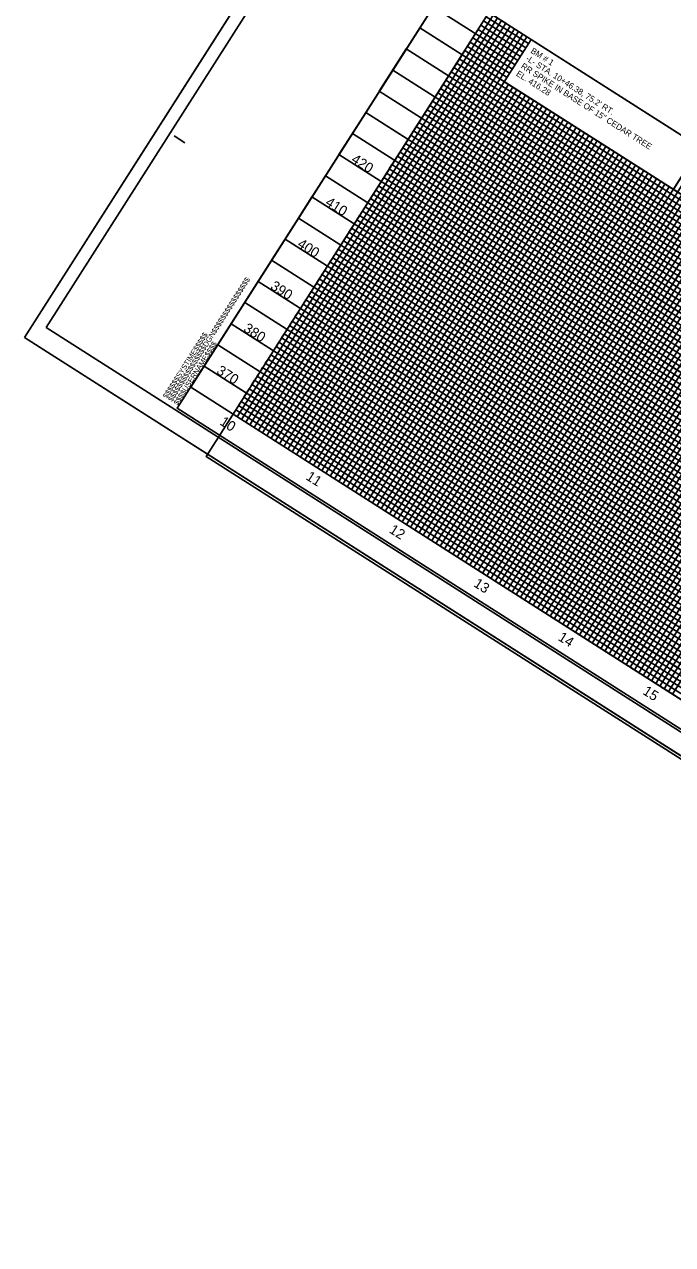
# Model space of a CAD drawing. Extents: x 2023536 to 2025544, y 819438 to 821266.
# Drawn here: x 2023536 to 2024183, y 819438 to 820655 of the extents above; entities that cross this region are included whole.
import ezdxf

# ---------------------------------------------------------------- set-up
doc = ezdxf.new("R2010")
doc.units = 0
for name, color, linetype in [('Default', 7, 'Continuous'), ('Exist Vertical Profile Horizontal Axis Label Major', 7, 'Continuous'), ('Exist Vertical Profile Vertical Axis Label', 7, 'Continuous'), ('Sheet Block System Information CELL', 7, 'Continuous'), ('Sheet Clip Boundary CELL', 7, 'Continuous'), ('Sheet Cutting Line CELL', 7, 'Continuous'), ('Sheet DOT Grid CELL', 7, 'Continuous'), ('Sheet Layout Profile Border Port 2', 7, 'Continuous'), ('Sheet Plan And Profile CELL', 7, 'Continuous'), ('Sheet Plot Border Inside CELL', 7, 'Continuous'), ('Sheet Plot Border Outside CELL', 7, 'Continuous'), ('Sheet Profile Grid Major CELL', 7, 'Continuous'), ('Sheet Profile Grid Middle CELL', 7, 'Continuous'), ('Sheet Profile Grid Minor CELL', 7, 'Continuous')]:
    doc.layers.add(name, color=color, linetype=linetype)

msp = doc.modelspace()

# ---------------------------------------------------------------- linework, layer by layer
at = {"layer": 'Default'}
msp.add_lwpolyline([(2024041.6, 820640.3), (2024210.3, 820532.8), (2024183.4, 820490.6), (2024014.8, 820598.1)], close=True, dxfattribs=at)
at = {"layer": 'Sheet Block System Information CELL'}
msp.add_line((2023688.6, 820272.4), (2023688.6, 820272.4), dxfattribs=at)
at = {"layer": 'Sheet Clip Boundary CELL'}
for points in [[(2023957.3, 820694), (2024252.9, 821157.8), (2024518.4, 820988.6), (2024450.6, 820880.9), (2024650, 820753), (2024719.3, 820860.6), (2025349.2, 820459.2), (2025268.5, 820332.6), (2025437.2, 820225.1), (2025222.2, 819887.8)], [(2023972.6, 820625), (2025153.2, 819872.5), (2024897.9, 819472), (2023717.3, 820224.4)]]:
    msp.add_lwpolyline(points, close=True, dxfattribs=at)
at = {"layer": 'Sheet Cutting Line CELL'}
for p, q in [((2024124.6, 821266.3), (2023536.1, 820342.9)), ((2023536.1, 820342.9), (2024955.8, 819438.1))]:
    msp.add_line(p, q, dxfattribs=at)
at = {"layer": 'Sheet DOT Grid CELL'}
for p, q in [((2023957.3, 820694), (2024041.6, 820640.3)), ((2023999.5, 820667.1), (2023744.2, 820266.6)), ((2023930.4, 820651.9), (2025195.4, 819845.7)), ((2024041.6, 820640.3), (2023786.3, 820239.7)), ((2023903.6, 820609.7), (2025168.5, 819803.5)), ((2024056.9, 820571.2), (2023828.5, 820212.8)), ((2023876.7, 820567.5), (2025141.6, 819761.3)), ((2024099.1, 820544.4), (2023870.7, 820186)), ((2024210.3, 820532.8), (2023955, 820132.2)), ((2023849.8, 820525.4), (2025114.8, 819719.2)), ((2024141.3, 820517.5), (2023912.8, 820159.1)), ((2024252.5, 820505.9), (2023997.2, 820105.3)), ((2023822.9, 820483.2), (2025087.9, 819677)), ((2024294.6, 820479), (2024039.3, 820078.5)), ((2024336.8, 820452.2), (2024081.5, 820051.6)), ((2023796.1, 820441), (2025061, 819634.8)), ((2024379, 820425.3), (2024123.7, 820024.7)), ((2023769.2, 820398.9), (2025034.1, 819592.7)), ((2024421.1, 820398.4), (2024165.8, 819997.9)), ((2023742.3, 820356.7), (2025007.3, 819550.5)), ((2023715.5, 820314.5), (2024980.4, 819508.4))]:
    msp.add_line(p, q, dxfattribs=at)
at = {"layer": 'Sheet Layout Profile Border Port 2'}
for points in [[(2024716.3, 820210.3), (2025180.1, 819914.7), (2024924.8, 819514.1), (2023744.2, 820266.6), (2023999.5, 820667.1), (2024041.6, 820640.3)], [(2024041.6, 820640.3), (2024014.8, 820598.1), (2024183.4, 820490.6), (2024210.3, 820532.8)]]:
    msp.add_lwpolyline(points, dxfattribs=at)
at = {"layer": 'Sheet Plan And Profile CELL'}
for p, q in [((2023685.6, 820544), (2023696.2, 820537.3)), ((2024967, 819487.3), (2023702, 820293.5)), ((2023688.6, 820272.4), (2023688.6, 820272.4)), ((2023688.6, 820272.4), (2023688.6, 820272.4)), ((2023688.6, 820272.4), (2023688.6, 820272.4)), ((2023688.6, 820272.4), (2023688.6, 820272.4)), ((2023688.6, 820272.4), (2023688.6, 820272.4))]:
    msp.add_line(p, q, dxfattribs=at)
msp.add_lwpolyline([(2025517.9, 820351.6), (2024252.9, 821157.8), (2023688.6, 820272.4), (2024953.5, 819466.2)], close=True, dxfattribs=at)
at = {"layer": 'Sheet Plot Border Inside CELL'}
msp.add_lwpolyline([(2023557.8, 820352.8), (2024962.7, 819457.4), (2025529.7, 820347), (2024124.8, 821242.4)], close=True, dxfattribs=at)
at = {"layer": 'Sheet Plot Border Outside CELL'}
msp.add_lwpolyline([(2023536.1, 820342.9), (2024955.8, 819438.1), (2025544.3, 820361.5), (2024124.6, 821266.3)], close=True, dxfattribs=at)
at = {"layer": 'Sheet Profile Grid Major CELL'}
for points in [[(2023957.3, 820694), (2023702, 820293.5)], [(2023957.3, 820694), (2024041.6, 820640.3)], [(2023744.2, 820266.6), (2023999.5, 820667.1), (2024041.6, 820640.3)], [(2025195.4, 819845.7), (2023930.4, 820651.9), (2023903.6, 820609.7), (2025168.5, 819803.5)], [(2024014.8, 820598.1), (2023786.3, 820239.7)], [(2023828.5, 820212.8), (2024056.9, 820571.2)], [(2025141.6, 819761.3), (2023876.7, 820567.5), (2023849.8, 820525.4), (2025114.8, 819719.2)], [(2024099.1, 820544.4), (2023870.7, 820186)], [(2024210.3, 820532.8), (2023955, 820132.2)], [(2023912.8, 820159.1), (2024141.3, 820517.5)], [(2023997.2, 820105.3), (2024252.5, 820505.9), (2024294.6, 820479), (2024039.3, 820078.5)], [(2025087.9, 819677), (2023822.9, 820483.2), (2023796.1, 820441), (2025061, 819634.8)], [(2024081.5, 820051.6), (2024336.8, 820452.2), (2024379, 820425.3), (2024123.7, 820024.7)], [(2025034.1, 819592.7), (2023769.2, 820398.9), (2023742.3, 820356.7), (2025007.3, 819550.5)], [(2024165.8, 819997.9), (2024421.1, 820398.4), (2024463.3, 820371.5), (2024208, 819971)], [(2024980.4, 819508.4), (2023715.5, 820314.5)]]:
    msp.add_lwpolyline(points, dxfattribs=at)
at = {"layer": 'Sheet Profile Grid Middle CELL'}
for p, q in [((2023943.9, 820672.9), (2024028.2, 820619.2)), ((2023917, 820630.8), (2023890.1, 820588.6)), ((2025181.9, 819824.6), (2023917, 820630.8)), ((2023890.1, 820588.6), (2025155.1, 819782.4)), ((2023863.3, 820546.4), (2023836.4, 820504.3)), ((2025128.2, 819740.3), (2023863.3, 820546.4)), ((2023836.4, 820504.3), (2025101.3, 819698.1)), ((2023809.5, 820462.1), (2023782.6, 820420)), ((2025074.4, 819655.9), (2023809.5, 820462.1)), ((2023782.6, 820420), (2025047.6, 819613.8)), ((2023755.8, 820377.8), (2023728.9, 820335.6)), ((2025020.7, 819571.6), (2023755.8, 820377.8)), ((2023728.9, 820335.6), (2024993.8, 819529.4))]:
    msp.add_line(p, q, dxfattribs=at)
for points in [[(2023765.3, 820253.1), (2024020.6, 820653.7), (2024041.6, 820640.3)], [(2024035.9, 820584.7), (2023807.4, 820226.3)], [(2023849.6, 820199.4), (2024078, 820557.8)], [(2024120.2, 820530.9), (2023891.8, 820172.5)], [(2024210.3, 820532.8), (2024231.4, 820519.3), (2023976.1, 820118.8)], [(2023933.9, 820145.7), (2024162.3, 820504.1)], [(2024018.3, 820091.9), (2024273.5, 820492.5), (2024315.7, 820465.6), (2024060.4, 820065)], [(2024102.6, 820038.2), (2024357.9, 820438.7), (2024400, 820411.9), (2024144.7, 820011.3)]]:
    msp.add_lwpolyline(points, dxfattribs=at)
at = {"layer": 'Sheet Profile Grid Minor CELL'}
for points in [[(2023748.4, 820263.9), (2024003.7, 820664.5), (2024007.9, 820661.8), (2023752.6, 820261.2)], [(2024039, 820636.1), (2023996.8, 820662.9)], [(2023756.8, 820258.5), (2024012.1, 820659.1), (2024016.3, 820656.4), (2023761.1, 820255.8)], [(2023769.5, 820250.5), (2024024.8, 820651), (2024029, 820648.3), (2023773.7, 820247.8)], [(2024025.5, 820615), (2023983.4, 820641.8), (2023986, 820646.1), (2023988.7, 820650.3), (2024030.9, 820623.4)], [(2024033.6, 820627.6), (2023991.4, 820654.5), (2023994.1, 820658.7), (2024036.3, 820631.8)], [(2023777.9, 820245.1), (2024033.2, 820645.6), (2024037.4, 820643), (2023782.1, 820242.4)], [(2023943, 820578.6), (2023945.7, 820582.8), (2023948.4, 820587), (2025129, 819834.6), (2025131.7, 819838.8), (2023951.1, 820591.3), (2023953.8, 820595.5), (2025134.4, 819843), (2025137.1, 819847.2), (2023956.5, 820599.7), (2023959.2, 820603.9), (2023961.9, 820608.1), (2025142.5, 819855.7), (2025145.2, 819859.9), (2023964.5, 820612.3), (2023967.2, 820616.6), (2025147.8, 819864.1), (2025150.5, 819868.3), (2023969.9, 820620.8), (2023972.6, 820625), (2023975.3, 820629.2), (2024017.5, 820602.3)], [(2024020.1, 820606.5), (2023978, 820633.4), (2023980.7, 820637.6), (2024022.8, 820610.8)], [(2023790.6, 820237), (2024019, 820595.4)], [(2024023.2, 820592.7), (2023794.8, 820234.3)], [(2023799, 820231.6), (2024027.4, 820590)], [(2024031.6, 820587.4), (2023803.2, 820229)], [(2023811.6, 820223.6), (2024040.1, 820582)], [(2024044.3, 820579.3), (2023815.9, 820220.9)], [(2025121, 819821.9), (2023940.4, 820574.4), (2023943, 820578.6), (2025123.7, 819826.2)], [(2023820.1, 820218.2), (2024048.5, 820576.6)], [(2024052.7, 820573.9), (2023824.3, 820215.5)], [(2023832.7, 820210.2), (2024061.2, 820568.5)], [(2024065.4, 820565.9), (2023836.9, 820207.5)], [(2025115.6, 819813.5), (2023935, 820566), (2023937.7, 820570.2), (2025118.3, 819817.7)], [(2023841.2, 820204.8), (2024069.6, 820563.2)], [(2024073.8, 820560.5), (2023845.4, 820202.1)], [(2023853.8, 820196.7), (2024082.2, 820555.1)], [(2025107.5, 819800.9), (2023926.9, 820553.3), (2023929.6, 820557.5), (2025110.2, 819805.1)], [(2024086.4, 820552.4), (2023858, 820194)], [(2023862.2, 820191.3), (2024090.7, 820549.7)], [(2024094.9, 820547.1), (2023866.5, 820188.7)], [(2023874.9, 820183.3), (2024103.3, 820541.7)], [(2025102.2, 819792.4), (2023921.5, 820544.9), (2023924.2, 820549.1), (2025104.8, 819796.6)], [(2024107.5, 820539), (2023879.1, 820180.6)], [(2023883.3, 820177.9), (2024111.7, 820536.3)], [(2024116, 820533.6), (2023887.5, 820175.2)], [(2025094.1, 819779.8), (2023913.5, 820532.2), (2023916.2, 820536.4), (2025096.8, 819784)], [(2023959.2, 820129.5), (2024214.5, 820530.1), (2024218.7, 820527.4), (2023963.4, 820126.8)], [(2023896, 820169.8), (2024124.4, 820528.2)], [(2024128.6, 820525.6), (2023900.2, 820167.2)], [(2023904.4, 820164.5), (2024132.8, 820522.9)], [(2025088.7, 819771.3), (2023908.1, 820523.8), (2023910.8, 820528), (2025091.4, 819775.6)], [(2024137, 820520.2), (2023908.6, 820161.8)], [(2023967.7, 820124.2), (2024222.9, 820524.7), (2024227.2, 820522), (2023971.9, 820121.5)], [(2023980.3, 820116.1), (2024235.6, 820516.7), (2024239.8, 820514), (2023984.5, 820113.4)], [(2025075.3, 819750.3), (2023894.7, 820502.7), (2023897.4, 820506.9), (2025078, 819754.5)], [(2025080.7, 819758.7), (2023900, 820511.1), (2023902.7, 820515.4), (2025083.3, 819762.9)], [(2023917.1, 820156.4), (2024145.5, 820514.8)], [(2024149.7, 820512.1), (2023921.3, 820153.7)], [(2023925.5, 820151), (2024153.9, 820509.4)], [(2024158.1, 820506.7), (2023929.7, 820148.3)], [(2023988.7, 820110.7), (2024244, 820511.3), (2024248.2, 820508.6), (2023993, 820108)], [(2025067.2, 819737.6), (2023886.6, 820490.1), (2023889.3, 820494.3), (2025069.9, 819741.8)], [(2023938.1, 820143), (2024166.6, 820501.4)], [(2024170.8, 820498.7), (2023942.4, 820140.3)], [(2023946.6, 820137.6), (2024175, 820496)], [(2024179.2, 820493.3), (2023950.8, 820134.9)], [(2024001.4, 820102.7), (2024256.7, 820503.2), (2024260.9, 820500.5), (2024005.6, 820100)], [(2024009.8, 820097.3), (2024265.1, 820497.8), (2024269.3, 820495.2), (2024014, 820094.6)], [(2025061.8, 819729.2), (2023881.2, 820481.6), (2023883.9, 820485.8), (2025064.5, 819733.4)], [(2024022.5, 820089.2), (2024277.8, 820489.8), (2024282, 820487.1), (2024026.7, 820086.5)], [(2024030.9, 820083.8), (2024286.2, 820484.4), (2024290.4, 820481.7), (2024035.1, 820081.2)], [(2025053.8, 819716.5), (2023873.2, 820469), (2023875.9, 820473.2), (2025056.5, 819720.8)], [(2024043.6, 820075.8), (2024298.8, 820476.4), (2024303.1, 820473.7), (2024047.8, 820073.1)], [(2024052, 820070.4), (2024307.3, 820471), (2024311.5, 820468.3), (2024056.2, 820067.7)], [(2025048.4, 819708.1), (2023867.8, 820460.5), (2023870.5, 820464.8), (2025051.1, 819712.3)], [(2024064.6, 820062.4), (2024319.9, 820462.9), (2024324.1, 820460.2), (2024068.9, 820059.7)], [(2024073.1, 820057), (2024328.4, 820457.5), (2024332.6, 820454.9), (2024077.3, 820054.3)], [(2025035, 819687), (2023854.4, 820439.5), (2023857.1, 820443.7), (2025037.7, 819691.2)], [(2025040.3, 819695.5), (2023859.7, 820447.9), (2023862.4, 820452.1), (2025043, 819699.7)], [(2024085.7, 820048.9), (2024341, 820449.5), (2024345.2, 820446.8), (2024089.9, 820046.2)], [(2024094.2, 820043.5), (2024349.4, 820444.1), (2024353.7, 820441.4), (2024098.4, 820040.9)], [(2024106.8, 820035.5), (2024362.1, 820436), (2024366.3, 820433.4), (2024111, 820032.8)], [(2025021.5, 819665.9), (2023840.9, 820418.4), (2023843.6, 820422.6), (2025024.2, 819670.2)], [(2025026.9, 819674.4), (2023846.3, 820426.8), (2023849, 820431), (2025029.6, 819678.6)], [(2024115.2, 820030.1), (2024370.5, 820430.7), (2024374.7, 820428), (2024119.4, 820027.4)], [(2024127.9, 820022), (2024383.2, 820422.6), (2024387.4, 820419.9), (2024132.1, 820019.4)], [(2025013.5, 819653.3), (2023832.9, 820405.7), (2023835.6, 820409.9), (2025016.2, 819657.5)], [(2024136.3, 820016.7), (2024391.6, 820417.2), (2024395.8, 820414.5), (2024140.5, 820014)], [(2024149, 820008.6), (2024404.3, 820409.2), (2024408.5, 820406.5), (2024153.2, 820005.9)], [(2025008.1, 819644.9), (2023827.5, 820397.3), (2023830.2, 820401.5), (2025010.8, 819649.1)], [(2024157.4, 820003.2), (2024412.7, 820403.8), (2024416.9, 820401.1), (2024161.6, 820000.5)], [(2024170, 819995.2), (2024425.3, 820395.7), (2024429.6, 820393), (2024174.3, 819992.5)], [(2025000, 819632.2), (2023819.4, 820384.6), (2023822.1, 820388.9), (2025002.7, 819636.4)], [(2024178.5, 819989.8), (2024433.8, 820390.4), (2024438, 820387.7), (2024182.7, 819987.1)], [(2024994.7, 819623.8), (2023814.1, 820376.2), (2023816.7, 820380.4), (2024997.3, 819628)], [(2024981.2, 819602.7), (2023800.6, 820355.1), (2023803.3, 820359.3), (2024983.9, 819606.9)], [(2024986.6, 819611.1), (2023806, 820363.6), (2023808.7, 820367.8), (2024989.3, 819615.3)], [(2024973.2, 819590), (2023792.6, 820342.5), (2023795.2, 820346.7), (2024975.9, 819594.3)], [(2024967.8, 819581.6), (2023787.2, 820334), (2023789.9, 820338.3), (2024970.5, 819585.8)], [(2023779.1, 820321.4), (2023781.8, 820325.6), (2024962.4, 819573.2)], [(2023746.9, 820270.8), (2024927.5, 819518.4), (2024930.2, 819522.6), (2023749.6, 820275), (2023752.2, 820279.2), (2024932.9, 819526.8), (2024935.5, 819531), (2023754.9, 820283.5), (2023757.6, 820287.7), (2023760.3, 820291.9), (2024940.9, 819539.4), (2024943.6, 819543.7), (2023763, 820296.1), (2023765.7, 820300.3), (2024946.3, 819547.9), (2024949, 819552.1), (2023768.4, 820304.5), (2023771.1, 820308.7), (2023773.7, 820313), (2024954.4, 819560.5), (2024957, 819564.7), (2023776.4, 820317.2), (2023779.1, 820321.4), (2024959.7, 819569)]]:
    msp.add_lwpolyline(points, dxfattribs=at)

# ---------------------------------------------------------------- texts
at = {"layer": 'Default'}
for s, p in [('BM # 1', (2024040.5, 820627.4)), ('RR SPIKE IN BASE OF 15" CEDAR TREE', (2024030.8, 820612.2)), ("-L- STA. 10+46.38, 75.2' RT.", (2024035.7, 820619.8)), ('EL. 416.28', (2024026, 820604.6))]:
    msp.add_text(s, height=6, rotation=327.4893, dxfattribs=at).set_placement(p)
at = {"layer": 'Exist Vertical Profile Horizontal Axis Label Major'}
for s, p in [('10', (2023730.2, 820256.6)), ('11', (2023816.1, 820201.9)), ('12', (2023899.2, 820148.9)), ('13', (2023983.4, 820095.2)), ('14', (2024067.6, 820041.6)), ('15', (2024152, 819987.8))]:
    msp.add_text(s, height=10, rotation=327.4893, dxfattribs=at).set_placement(p)
at = {"layer": 'Exist Vertical Profile Vertical Axis Label'}
for s, p in [('420', (2023861.3, 820518.4)), ('410', (2023835.4, 820475.5)), ('400', (2023807.5, 820434)), ('390', (2023780.7, 820391.9)), ('380', (2023753.8, 820349.7)), ('370', (2023726.9, 820307.5))]:
    msp.add_text(s, height=10, rotation=327.4893, dxfattribs=at).set_placement(p)
at = {"layer": 'Sheet Block System Information CELL'}
for s, p in [('$$$$$$$$$$$$$$$$DGN$$$$$$$$$$$$$$$$', (2023683.4, 820278.5)), ('$$$$$$SYSTIME$$$$$', (2023678.3, 820281.7)), ('$$$$USERNAME$$$$', (2023689, 820275))]:
    msp.add_text(s, height=5.25, rotation=57.4893, dxfattribs=at).set_placement(p)

doc.saveas('drawing.dxf')
